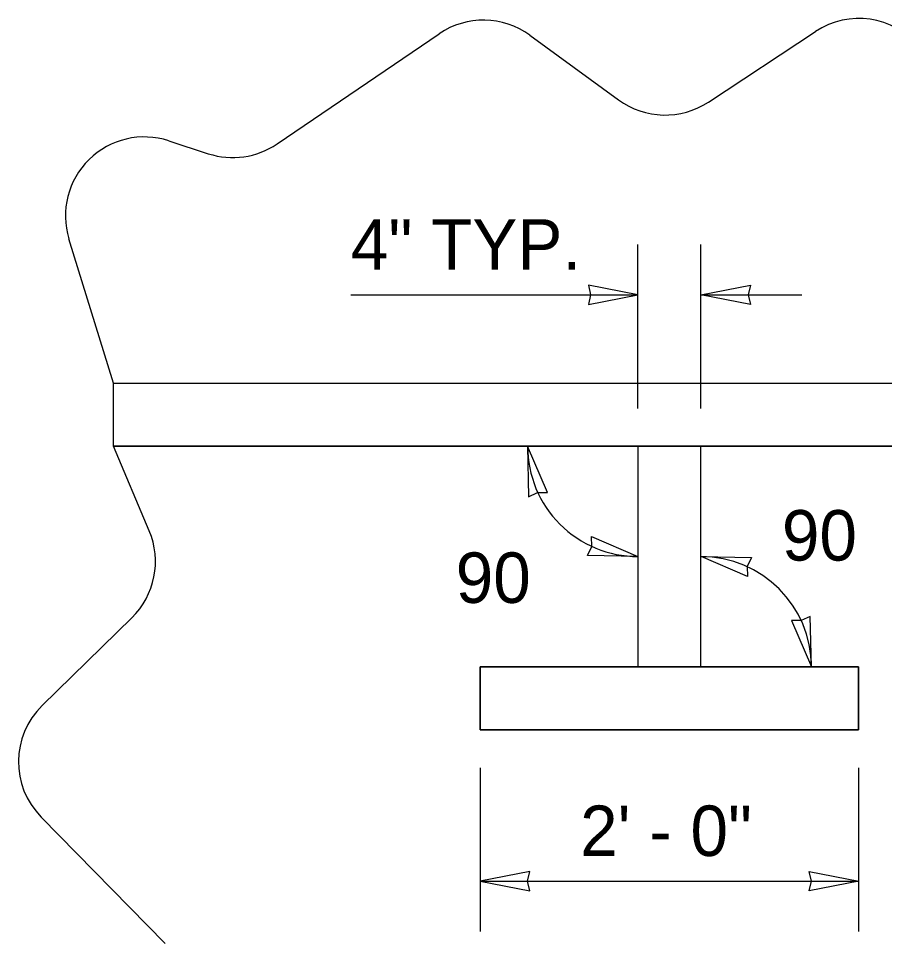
# Model space of a CAD drawing. Extents: x 99862 to 104211, y 98939 to 105076.
# Drawn here: x 101963.4 to 102238.1, y 100490.7 to 100784.1 of the extents above; entities that cross this region are included whole.
import ezdxf

# ---------------------------------------------------------------- set-up
doc = ezdxf.new("R2010")
doc.units = 0
for name, color, linetype in [('Level 15', 7, 'Continuous'), ('Level 17', 7, 'Continuous'), ('Level 20', 7, 'Continuous'), ('Level 5', 7, 'Continuous'), ('Level 50', 7, 'Continuous')]:
    doc.layers.add(name, color=color, linetype=linetype)

msp = doc.modelspace()

# ---------------------------------------------------------------- linework, layer by layer
at = {"layer": 'Level 15'}
for p, q in [((102159.89, 100660.46), (102159.89, 100712.46)), ((102179.89, 100660.46), (102179.89, 100712.46)), ((102068.8, 100696.46), (102159.89, 100696.46)), ((102179.89, 100696.46), (102211.89, 100696.46)), ((102109.89, 100546.46), (102109.89, 100494.46)), ((102229.89, 100546.46), (102229.89, 100494.46)), ((102109.89, 100510.46), (102229.89, 100510.46))]:
    msp.add_line(p, q, dxfattribs=at)
for points in [[(102159.89, 100696.46), (102144.17, 100699.55), (102144.9, 100696.46), (102144.17, 100693.38)], [(102179.89, 100696.46), (102195.62, 100699.55), (102194.89, 100696.46), (102195.62, 100693.38)], [(102124.9, 100648.46), (102125.23, 100632.44), (102128.09, 100633.81), (102131.25, 100633.75)], [(102159.9, 100613.46), (102143.87, 100613.79), (102145.24, 100616.65), (102145.19, 100619.82)], [(102179.9, 100613.46), (102195.92, 100613.13), (102194.55, 100610.27), (102194.6, 100607.1)], [(102214.9, 100578.46), (102214.56, 100594.48), (102211.7, 100593.12), (102208.54, 100593.17)], [(102109.9, 100510.46), (102125.62, 100507.38), (102124.89, 100510.46), (102125.62, 100513.55)], [(102229.9, 100510.46), (102214.17, 100507.38), (102214.9, 100510.46), (102214.17, 100513.55)]]:
    msp.add_lwpolyline(points, close=True, dxfattribs=at)
for centre, start, end in [((102159.89, 100648.46), 179.9999, 270), ((102179.89, 100578.46), 0, 90)]:
    msp.add_arc(centre, 35, start, end, dxfattribs=at)
at = {"layer": 'Level 17'}
for p, q in [((101993.53, 100668.46), (102358.78, 100668.46)), ((101993.53, 100648.46), (102358.78, 100648.46))]:
    msp.add_line(p, q, dxfattribs=at)
for points in [[(101993.53, 100668.46), (102358.78, 100668.46), (102358.78, 100648.46), (101993.53, 100648.46)], [(102159.89, 100578.46), (102179.89, 100578.46), (102179.89, 100648.46), (102159.89, 100648.46)], [(102109.89, 100578.46), (102229.89, 100578.46), (102229.89, 100558.46), (102109.89, 100558.46)]]:
    msp.add_lwpolyline(points, close=True, dxfattribs=at)
at = {"layer": 'Level 5'}
for p, q in [((102179.89, 100648.46), (102159.89, 100648.46)), ((102159.89, 100648.46), (102159.89, 100578.46)), ((102179.89, 100578.46), (102179.89, 100648.46)), ((102229.89, 100578.46), (102109.89, 100578.46)), ((102109.89, 100578.46), (102109.89, 100558.46)), ((102159.89, 100578.46), (102179.89, 100578.46)), ((102229.89, 100558.46), (102229.89, 100578.46)), ((102109.89, 100558.46), (102229.89, 100558.46))]:
    msp.add_line(p, q, dxfattribs=at)
msp.add_lwpolyline([(101993.53, 100668.46), (102358.78, 100668.46), (102358.78, 100648.46), (101993.53, 100648.46)], close=True, dxfattribs=at)
at = {"layer": 'Level 50'}
for points in [[(102045.45, 100744.35), (102096.86, 100779.3)], [(102125.65, 100778.82), (102153.74, 100758.33)], [(102182.23, 100757.65), (102216.17, 100780.02)], [(102011.09, 100745.34), (102023.64, 100741.25)], [(102004.9, 100621.63), (101993.53, 100648.46), (101993.53, 100668.46), (101979.45, 100714.22)], [(101970.95, 100566.17), (101999.37, 100594.03)], [(102009.91, 100490.7), (101970.59, 100530.82)]]:
    msp.add_lwpolyline(points, dxfattribs=at)
for centre, start, end in [((102110.91, 100758.63), 53.8807, 124.2157), ((102229.93, 100759.14), 40.1009, 123.3885), ((102168.47, 100778.52), 233.8807, 303.3885), ((102003.34, 100721.57), 71.9395, 197.1049), ((102031.39, 100765.02), 251.9395, 304.2157), ((101981.88, 100611.88), 314.4213, 22.9572), ((101988.45, 100548.32), 134.4213, 224.4213)]:
    msp.add_arc(centre, 25, start, end, dxfattribs=at)

# ---------------------------------------------------------------- texts
at = {"layer": 'Level 20'}
for s, p in [('4" TYP.', (102068.87, 100704.46)), ('90', (102205.55, 100612.18)), ('90', (102102.11, 100598.75)), ('2\' - 0"', (102141.56, 100518.47))]:
    msp.add_text(s, height=16, dxfattribs=at).set_placement(p)

doc.saveas('drawing.dxf')
